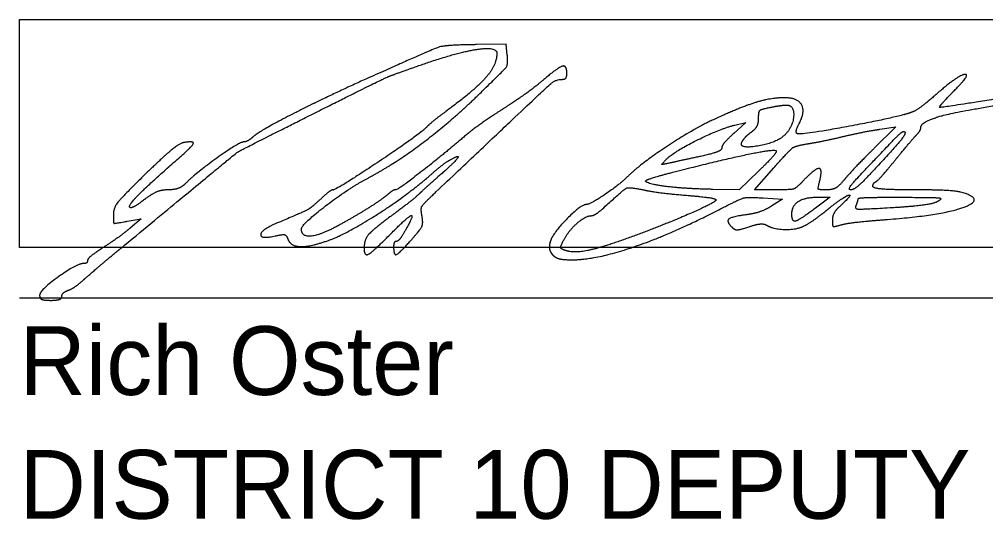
# Model space of a CAD drawing. Extents: x -84548 to 2262448, y -162180 to 525962.
# Drawn here: x 133817 to 144196, y -31532 to -26153 of the extents above; entities that cross this region are included whole.
import ezdxf

# ---------------------------------------------------------------- set-up
doc = ezdxf.new("R2010")
doc.units = 0
doc.layers.add('GM_X_County', color=7, linetype='Continuous')
doc.layers.add('GM_X_Section', color=7, linetype='Continuous')

msp = doc.modelspace()

# ---------------------------------------------------------------- linework, layer by layer
at = {"layer": 'GM_X_County'}
msp.add_line((133817, -29146), (152297, -29146), dxfattribs=at)
msp.add_lwpolyline([(133817, -28607), (133817, -26153), (152318, -26153), (152318, -28607)], close=True, dxfattribs=at)
at = {"layer": 'GM_X_Section'}
msp.add_line((134035, -29120), (134035, -29120), dxfattribs=at)
for points in [[(139058, -26537), (139045, -26421), (138728, -26425)], [(141501, -27290), (141619, -27262), (141490, -27380)], [(143058, -27335), (143230, -27310), (142999, -27539)], [(141756, -27785), (141549, -27986), (141267, -27981)], [(141929, -27986), (141713, -27986), (141920, -27750)], [(141805, -28073), (142012, -28085), (141899, -28158)], [(142391, -28065), (142524, -28065), (142368, -28182)], [(134976, -28324), (135124, -28298), (135006, -28398)]]:
    msp.add_lwpolyline(points, dxfattribs=at)
for points in [[(138728, -26425), (138398, -26429), (138259, -26472), (137540, -26795)], [(138213, -26615), (138551, -26500), (138946, -26447), (138946, -26517)], [(138946, -26517), (138946, -26644), (138708, -26915), (138396, -27145)], [(138741, -26972), (139026, -26696), (139069, -26636), (139058, -26537)], [(137104, -27102), (137697, -26805), (137832, -26746), (138213, -26615)], [(139698, -26738), (139698, -26643), (139605, -26669), (139438, -26810)], [(139649, -26798), (139676, -26798), (139698, -26771), (139698, -26738)], [(143852, -26926), (144047, -26732), (143891, -26760), (143664, -26960)], [(137540, -26795), (137117, -26985), (136399, -27352), (136329, -27415)], [(138292, -28008), (139461, -26901), (139577, -26798), (139649, -26798)], [(139438, -26810), (139353, -26883), (139158, -27022), (139005, -27121)], [(137562, -27859), (137846, -27709), (138451, -27253), (138741, -26972)], [(143664, -26960), (143563, -27050), (143444, -27136), (143401, -27152)], [(143500, -27314), (143500, -27238), (144147, -27094), (145048, -26971)], [(144363, -27000), (143728, -27103), (143682, -27096), (143852, -26926)], [(142035, -26996), (141890, -26996), (141564, -27097), (141271, -27232)], [(141881, -27099), (141949, -27086), (142029, -27075), (142059, -27075)], [(142194, -27271), (142261, -27145), (142175, -26996), (142035, -26996)], [(142059, -27075), (142139, -27075), (142128, -27301), (142045, -27389)], [(134946, -28582), (136132, -27600), (136183, -27565), (137104, -27102)], [(138396, -27145), (138317, -27203), (138221, -27281), (138183, -27320)], [(139005, -27121), (138853, -27219), (138675, -27346), (138609, -27402)], [(141757, -27216), (141757, -27145), (141785, -27119), (141881, -27099)], [(143401, -27152), (143256, -27205), (142191, -27403), (142169, -27381)], [(141271, -27232), (141049, -27335), (140476, -27717), (140340, -27853)], [(140767, -27657), (140844, -27578), (141346, -27327), (141501, -27290)], [(141686, -27360), (141725, -27331), (141757, -27267), (141757, -27216)], [(142169, -27381), (142157, -27369), (142168, -27319), (142194, -27271)], [(138183, -27320), (138105, -27398), (137224, -27986), (137185, -27986)], [(141490, -27380), (141419, -27445), (141361, -27515), (141361, -27537)], [(142045, -27389), (141958, -27480), (141530, -27551), (141582, -27465)], [(141582, -27465), (141599, -27436), (141646, -27388), (141686, -27360)], [(142668, -27412), (142788, -27384), (142963, -27349), (143058, -27335)], [(143326, -27362), (143344, -27381), (143218, -27534), (142940, -27831)], [(143196, -27461), (143257, -27396), (143315, -27352), (143326, -27362)], [(143222, -27669), (143320, -27549), (143423, -27427), (143450, -27399)], [(143450, -27399), (143478, -27370), (143500, -27332), (143500, -27314)], [(135582, -27478), (135539, -27485), (135352, -27640), (135166, -27822)], [(135530, -27644), (135677, -27517), (135694, -27459), (135582, -27478)], [(136228, -27471), (136182, -27471), (135709, -27808), (135608, -27912)], [(136329, -27415), (136295, -27446), (136249, -27471), (136228, -27471)], [(138609, -27402), (138374, -27605), (137884, -27986), (137859, -27986)], [(141920, -27750), (142091, -27556), (142156, -27511), (142289, -27490)], [(142289, -27490), (142378, -27475), (142548, -27441), (142668, -27412)], [(142749, -27986), (142708, -27986), (142821, -27853), (143196, -27461)], [(140835, -27797), (141346, -27666), (141924, -27545), (141945, -27565)], [(141361, -27537), (141361, -27559), (141259, -27599), (141134, -27626)], [(141945, -27565), (141955, -27576), (141870, -27675), (141756, -27785)], [(142999, -27539), (142871, -27665), (142727, -27817), (142678, -27877)], [(135002, -28174), (134983, -28154), (135230, -27906), (135530, -27644)], [(138233, -27826), (138309, -27759), (138405, -27685), (138446, -27663)], [(138446, -27663), (138555, -27601), (138489, -27695), (138317, -27844)], [(140807, -27697), (140718, -27716), (140714, -27712), (140767, -27657)], [(141134, -27626), (141009, -27653), (140862, -27685), (140807, -27697)], [(143015, -27900), (143031, -27892), (143125, -27789), (143222, -27669)], [(140545, -27895), (140535, -27885), (140665, -27841), (140835, -27797)], [(142414, -27887), (142447, -27756), (142363, -27756), (142238, -27887)], [(135166, -27822), (134921, -28062), (134827, -28181), (134827, -28252)], [(135608, -27912), (135569, -27952), (135483, -27986), (135417, -27986)], [(136847, -28408), (136847, -28358), (137353, -27969), (137562, -27859)], [(137128, -28533), (137324, -28466), (137992, -28038), (138233, -27826)], [(138317, -27844), (138240, -27911), (138147, -27995), (138111, -28030)], [(140340, -27853), (140259, -27933), (139946, -28144), (139907, -28144)], [(141267, -27981), (140976, -27975), (140579, -27929), (140545, -27895)], [(142238, -27887), (142161, -27968), (142108, -27986), (141929, -27986)], [(142490, -27986), (142403, -27986), (142393, -27973), (142414, -27887)], [(142678, -27877), (142624, -27943), (142551, -27986), (142490, -27986)], [(142940, -27831), (142861, -27916), (142775, -27986), (142749, -27986)], [(142985, -27949), (142985, -27929), (142998, -27907), (143015, -27900)], [(135417, -27986), (135349, -27986), (135239, -28030), (135160, -28090)], [(137185, -27986), (137172, -27986), (137112, -28030), (137054, -28085)], [(137859, -27986), (137845, -27986), (137812, -28004), (137786, -28026)], [(138142, -28269), (138126, -28189), (138157, -28135), (138292, -28008)], [(140077, -28193), (140310, -27980), (140368, -27954), (140520, -27986)], [(140520, -27986), (140602, -28004), (140817, -28031), (140999, -28046)], [(143411, -27986), (143177, -27986), (142985, -27969), (142985, -27949)], [(143143, -28304), (143731, -28259), (144199, -28084), (143927, -28011)], [(143927, -28011), (143877, -27998), (143645, -27986), (143411, -27986)], [(135160, -28090), (135085, -28148), (135014, -28185), (135002, -28174)], [(137054, -28085), (136952, -28179), (136876, -28221), (136580, -28346)], [(137786, -28026), (137709, -28091), (137456, -28252), (137262, -28360)], [(138111, -28030), (138074, -28066), (137945, -28168), (137823, -28258)], [(141296, -28102), (141246, -28145), (140707, -28376), (140371, -28499)], [(140999, -28046), (141180, -28061), (141314, -28086), (141296, -28102)], [(141371, -28179), (141555, -28083), (141638, -28063), (141805, -28073)], [(142114, -28249), (142114, -28157), (142253, -28065), (142391, -28065)], [(142502, -28194), (142674, -28055), (142776, -28030), (142629, -28164)], [(142806, -28151), (142818, -28122), (142827, -28090), (142827, -28081)], [(142827, -28081), (142827, -28072), (143036, -28065), (143292, -28066)], [(143683, -28110), (143643, -28134), (143424, -28165), (143198, -28179)], [(143292, -28066), (143646, -28067), (143740, -28077), (143683, -28110)], [(139907, -28144), (139849, -28144), (139548, -28452), (139520, -28540)], [(139754, -28738), (140016, -28738), (140857, -28447), (141371, -28179)], [(139958, -28264), (139981, -28263), (140035, -28231), (140077, -28193)], [(141899, -28158), (141837, -28199), (141717, -28241), (141632, -28253)], [(142368, -28182), (142200, -28310), (142114, -28333), (142114, -28249)], [(142252, -28371), (142296, -28349), (142408, -28269), (142502, -28194)], [(142629, -28164), (142585, -28203), (142549, -28270), (142549, -28313)], [(143198, -28179), (142862, -28199), (142790, -28194), (142806, -28151)], [(134827, -28252), (134827, -28344), (134837, -28349), (134976, -28324)], [(137823, -28258), (137613, -28414), (137520, -28523), (137520, -28617)], [(137784, -28481), (137987, -28275), (138061, -28250), (137964, -28421)], [(138035, -28515), (138128, -28409), (138156, -28344), (138142, -28269)], [(139664, -28527), (139715, -28428), (139896, -28266), (139958, -28264)], [(141632, -28253), (141466, -28275), (141408, -28325), (141472, -28389)], [(142549, -28313), (142549, -28375), (142567, -28385), (142639, -28363)], [(142639, -28363), (142688, -28348), (142915, -28322), (143143, -28304)], [(135006, -28398), (134940, -28453), (134811, -28546), (134719, -28606)], [(136580, -28346), (136415, -28416), (136404, -28517), (136565, -28482)], [(137262, -28360), (137066, -28470), (136847, -28495), (136847, -28408)], [(137964, -28421), (137927, -28486), (137883, -28540), (137867, -28540)], [(141472, -28389), (141500, -28417), (141558, -28415), (141654, -28383)], [(141654, -28383), (141732, -28357), (141816, -28349), (141841, -28365)], [(141841, -28365), (141915, -28410), (142167, -28415), (142252, -28371)], [(136565, -28482), (136648, -28463), (136685, -28473), (136702, -28518)], [(136702, -28518), (136731, -28592), (136935, -28600), (137128, -28533)], [(137520, -28617), (137520, -28702), (137613, -28654), (137784, -28481)], [(137837, -28599), (137837, -28695), (137899, -28669), (138035, -28515)], [(137867, -28540), (137850, -28540), (137837, -28567), (137837, -28599)], [(139520, -28540), (139506, -28586), (139515, -28649), (139541, -28680)], [(139669, -28633), (139631, -28618), (139630, -28592), (139664, -28527)], [(140371, -28499), (140069, -28610), (139758, -28670), (139669, -28633)], [(134511, -28950), (134565, -28901), (134761, -28735), (134946, -28582)], [(134719, -28606), (134626, -28665), (134550, -28728), (134550, -28746)], [(134550, -28746), (134550, -28763), (134532, -28778), (134510, -28778)], [(139541, -28680), (139569, -28714), (139658, -28738), (139754, -28738)], [(134510, -28778), (134435, -28778), (134035, -29066), (134035, -29120)], [(134342, -29066), (134380, -29052), (134456, -29000), (134511, -28950)], [(134035, -29120), (134035, -29153), (134081, -29174), (134154, -29174)], [(134154, -29174), (134220, -29174), (134273, -29155), (134273, -29133)], [(134273, -29133), (134273, -29110), (134304, -29080), (134342, -29066)]]:
    msp.add_open_spline(points, degree=2, dxfattribs=at)

# ---------------------------------------------------------------- texts
for s, p in [('Rich Oster', (133817, -30191)), ('DISTRICT 10 DEPUTY DIRECTOR', (133817, -31522))]:
    msp.add_text(s, height=739.2, dxfattribs=at).set_placement(p)

doc.saveas('drawing.dxf')
